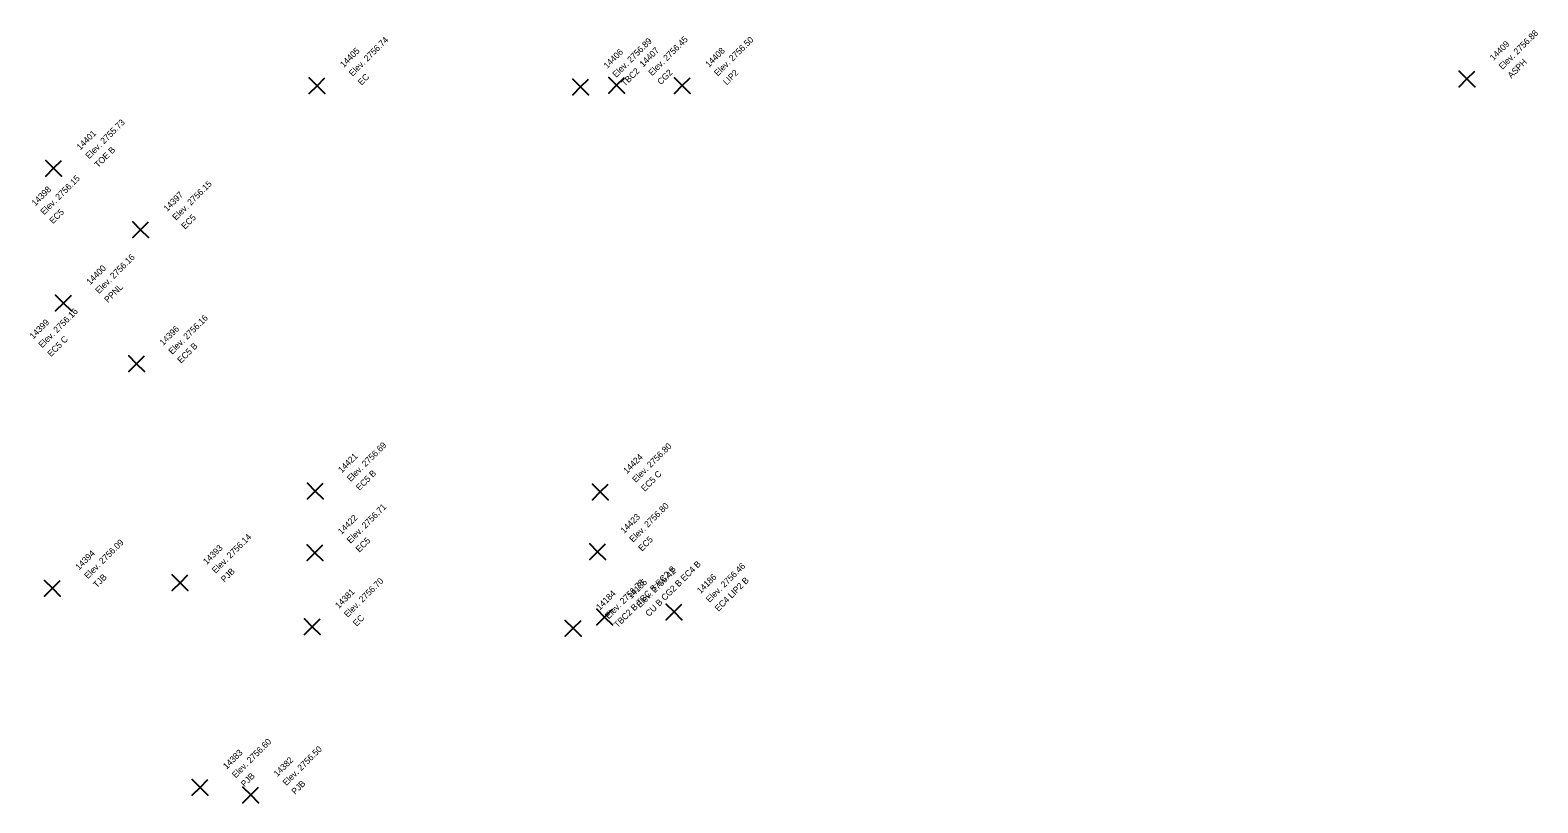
# Model space of a CAD drawing. Extents: x 2493999 to 2503109, y 700767 to 706646.
# Drawn here: x 2502325.44 to 2502354.25, y 703229.15 to 703243.91 of the extents above; entities that cross this region are included whole.
import ezdxf

# ---------------------------------------------------------------- set-up
doc = ezdxf.new("R2010")
doc.units = 0
doc.layers.add('ALG_CL_BLUE_Horiz', color=7, linetype='Continuous')
doc.layers.add('DES_SURFACE_Existing-Ground', color=7, linetype='Continuous')

msp = doc.modelspace()

# ---------------------------------------------------------------- linework, layer by layer
at = {"layer": 'ALG_CL_BLUE_Horiz'}
for points in [[(2502330.92, 703242.852), (2502330.77, 703243.002), (2502330.92, 703242.852), (2502330.77, 703242.702), (2502330.92, 703242.852), (2502331.07, 703242.702), (2502330.92, 703242.852), (2502331.07, 703243.002)], [(2502335.954, 703242.83), (2502335.804, 703242.98), (2502335.954, 703242.83), (2502335.804, 703242.68), (2502335.954, 703242.83), (2502336.104, 703242.68), (2502335.954, 703242.83), (2502336.104, 703242.98)], [(2502336.642, 703242.861), (2502336.492, 703243.011), (2502336.642, 703242.861), (2502336.492, 703242.711), (2502336.642, 703242.861), (2502336.792, 703242.711), (2502336.642, 703242.861), (2502336.792, 703243.011)], [(2502337.899, 703242.855), (2502337.749, 703243.005), (2502337.899, 703242.855), (2502337.749, 703242.705), (2502337.899, 703242.855), (2502338.049, 703242.705), (2502337.899, 703242.855), (2502338.049, 703243.005)], [(2502352.892, 703242.983), (2502352.742, 703243.133), (2502352.892, 703242.983), (2502352.742, 703242.833), (2502352.892, 703242.983), (2502353.042, 703242.833), (2502352.892, 703242.983), (2502353.042, 703243.133)], [(2502325.885, 703241.275), (2502325.735, 703241.425), (2502325.885, 703241.275), (2502325.735, 703241.125), (2502325.885, 703241.275), (2502326.035, 703241.125), (2502325.885, 703241.275), (2502326.035, 703241.425)], [(2502327.546, 703240.101), (2502327.396, 703240.251), (2502327.546, 703240.101), (2502327.396, 703239.951), (2502327.546, 703240.101), (2502327.696, 703239.951), (2502327.546, 703240.101), (2502327.696, 703240.251)], [(2502326.073, 703238.698), (2502325.923, 703238.848), (2502326.073, 703238.698), (2502325.923, 703238.548), (2502326.073, 703238.698), (2502326.223, 703238.548), (2502326.073, 703238.698), (2502326.223, 703238.848)], [(2502327.471, 703237.539), (2502327.321, 703237.689), (2502327.471, 703237.539), (2502327.321, 703237.389), (2502327.471, 703237.539), (2502327.621, 703237.389), (2502327.471, 703237.539), (2502327.621, 703237.689)], [(2502330.883, 703235.106), (2502330.733, 703235.256), (2502330.883, 703235.106), (2502330.733, 703234.956), (2502330.883, 703235.106), (2502331.033, 703234.956), (2502330.883, 703235.106), (2502331.033, 703235.256)], [(2502336.332, 703235.088), (2502336.182, 703235.238), (2502336.332, 703235.088), (2502336.182, 703234.938), (2502336.332, 703235.088), (2502336.482, 703234.938), (2502336.332, 703235.088), (2502336.482, 703235.238)], [(2502330.879, 703233.927), (2502330.729, 703234.077), (2502330.879, 703233.927), (2502330.729, 703233.777), (2502330.879, 703233.927), (2502331.029, 703233.777), (2502330.879, 703233.927), (2502331.029, 703234.077)], [(2502336.279, 703233.947), (2502336.129, 703234.097), (2502336.279, 703233.947), (2502336.129, 703233.797), (2502336.279, 703233.947), (2502336.429, 703233.797), (2502336.279, 703233.947), (2502336.429, 703234.097)], [(2502325.861, 703233.248), (2502325.711, 703233.398), (2502325.861, 703233.248), (2502325.711, 703233.098), (2502325.861, 703233.248), (2502326.011, 703233.098), (2502325.861, 703233.248), (2502326.011, 703233.398)], [(2502328.302, 703233.353), (2502328.152, 703233.503), (2502328.302, 703233.353), (2502328.152, 703233.203), (2502328.302, 703233.353), (2502328.452, 703233.203), (2502328.302, 703233.353), (2502328.452, 703233.503)], [(2502336.413, 703232.698), (2502336.263, 703232.848), (2502336.413, 703232.698), (2502336.263, 703232.548), (2502336.413, 703232.698), (2502336.563, 703232.548), (2502336.413, 703232.698), (2502336.563, 703232.848)], [(2502337.74, 703232.796), (2502337.59, 703232.946), (2502337.74, 703232.796), (2502337.59, 703232.646), (2502337.74, 703232.796), (2502337.89, 703232.646), (2502337.74, 703232.796), (2502337.89, 703232.946)], [(2502330.826, 703232.512), (2502330.676, 703232.662), (2502330.826, 703232.512), (2502330.676, 703232.362), (2502330.826, 703232.512), (2502330.976, 703232.362), (2502330.826, 703232.512), (2502330.976, 703232.662)], [(2502335.813, 703232.483), (2502335.663, 703232.633), (2502335.813, 703232.483), (2502335.663, 703232.333), (2502335.813, 703232.483), (2502335.963, 703232.333), (2502335.813, 703232.483), (2502335.963, 703232.633)], [(2502328.683, 703229.441), (2502328.533, 703229.591), (2502328.683, 703229.441), (2502328.533, 703229.291), (2502328.683, 703229.441), (2502328.833, 703229.291), (2502328.683, 703229.441), (2502328.833, 703229.591)], [(2502329.651, 703229.297), (2502329.501, 703229.447), (2502329.651, 703229.297), (2502329.501, 703229.147), (2502329.651, 703229.297), (2502329.801, 703229.147), (2502329.651, 703229.297), (2502329.801, 703229.447)]]:
    msp.add_lwpolyline(points, dxfattribs=at)

# ---------------------------------------------------------------- texts
at = {"layer": 'DES_SURFACE_Existing-Ground'}
for s, p in [('Elev. 2756.74', (2502331.599, 703243.022)), ('Elev. 2756.89', (2502336.633, 703243)), ('Elev. 2756.45', (2502337.321, 703243.031)), ('Elev. 2756.50', (2502338.578, 703243.025)), ('Elev. 2756.88', (2502353.571, 703243.153)), ('14405', (2502331.429, 703243.191)), ('14406', (2502336.463, 703243.169)), ('14407', (2502337.151, 703243.2)), ('14408', (2502338.408, 703243.194)), ('14409', (2502353.401, 703243.322)), ('TBC2', (2502336.803, 703242.83)), ('ASPH', (2502353.741, 703242.983)), ('EC', (2502331.769, 703242.852)), ('CG2', (2502337.491, 703242.861)), ('LIP2', (2502338.748, 703242.855)), ('Elev. 2755.73', (2502326.564, 703241.445)), ('14401', (2502326.394, 703241.614)), ('TOE B', (2502326.734, 703241.275)), ('14398', (2502325.534, 703240.544)), ('Elev. 2756.15', (2502325.704, 703240.375)), ('Elev. 2756.15', (2502328.225, 703240.271)), ('14397', (2502328.055, 703240.44)), ('EC5', (2502325.874, 703240.205)), ('EC5', (2502328.395, 703240.101)), ('Elev. 2756.16', (2502326.752, 703238.868)), ('14400', (2502326.582, 703239.037)), ('PPNL', (2502326.922, 703238.698)), ('Elev. 2756.16', (2502325.666, 703237.834)), ('14399', (2502325.496, 703238.003)), ('Elev. 2756.16', (2502328.15, 703237.709)), ('EC5 C', (2502325.836, 703237.664)), ('14396', (2502327.98, 703237.878)), ('EC5 B', (2502328.32, 703237.539)), ('Elev. 2756.69', (2502331.562, 703235.276)), ('Elev. 2756.80', (2502337.011, 703235.258)), ('14421', (2502331.392, 703235.445)), ('14424', (2502336.841, 703235.427)), ('EC5 B', (2502331.732, 703235.106)), ('EC5 C', (2502337.181, 703235.088)), ('Elev. 2756.71', (2502331.558, 703234.097)), ('Elev. 2756.80', (2502336.958, 703234.117)), ('14422', (2502331.388, 703234.266)), ('14423', (2502336.788, 703234.286)), ('Elev. 2756.14', (2502328.981, 703233.523)), ('14394', (2502326.37, 703233.587)), ('Elev. 2756.09', (2502326.54, 703233.418)), ('14393', (2502328.811, 703233.692)), ('EC5', (2502331.728, 703233.927)), ('EC5', (2502337.128, 703233.947)), ('TBC2 B TBC B EC2 B', (2502336.662, 703232.483)), ('CU B CG2 B EC4 B', (2502337.262, 703232.698)), ('Elev. 2756.46', (2502338.419, 703232.966)), ('TJB', (2502326.71, 703233.248)), ('PJB', (2502329.151, 703233.353)), ('Elev. 2756.70', (2502331.505, 703232.682)), ('Elev. 2756.78', (2502336.492, 703232.653)), ('14185', (2502336.922, 703233.037)), ('Elev. 2756.42', (2502337.092, 703232.868)), ('14186', (2502338.249, 703233.135)), ('EC4 LIP2 B', (2502338.589, 703232.796)), ('14381', (2502331.335, 703232.851)), ('14184', (2502336.322, 703232.822)), ('EC', (2502331.675, 703232.512)), ('Elev. 2756.60', (2502329.362, 703229.611)), ('Elev. 2756.50', (2502330.33, 703229.467)), ('14383', (2502329.192, 703229.78)), ('14382', (2502330.16, 703229.636)), ('PJB', (2502329.532, 703229.441)), ('PJB', (2502330.5, 703229.297))]:
    msp.add_text(s, height=0.12, rotation=45, dxfattribs=at).set_placement(p)

doc.saveas('drawing.dxf')
